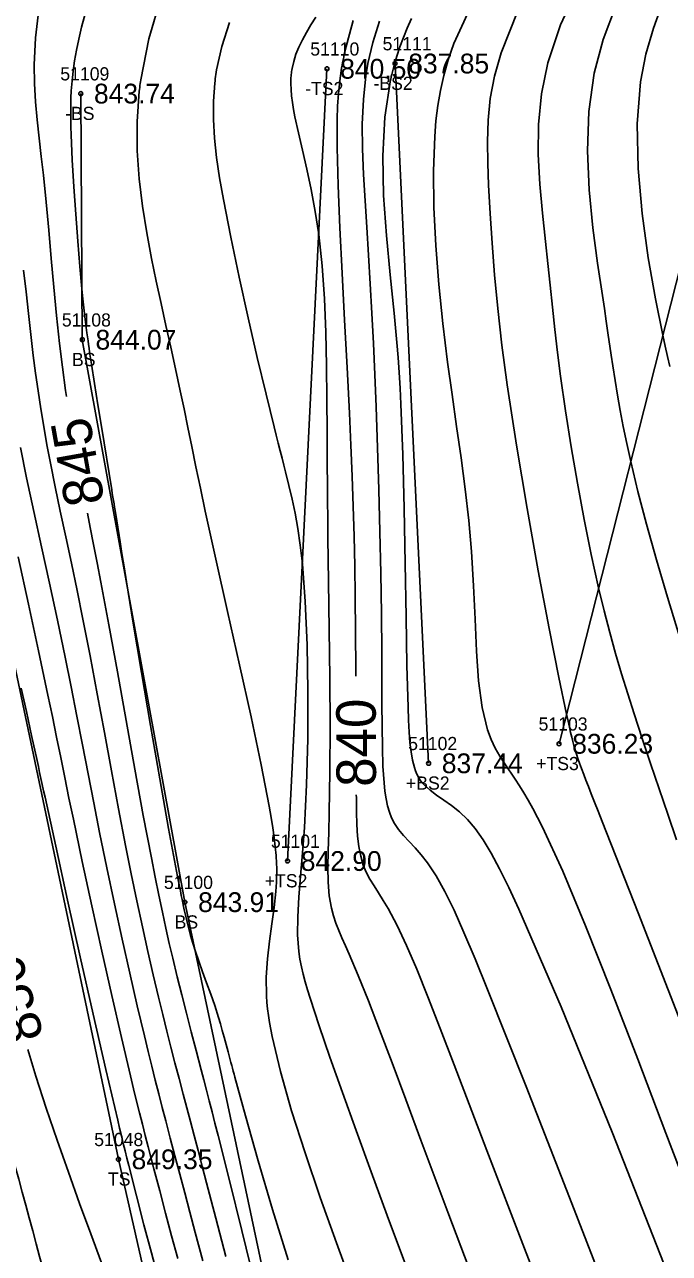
# Model space of a CAD drawing. Extents: x 1378535 to 1380697, y 997729 to 1000024.
# Drawn here: x 1380567 to 1380615.9, y 997912.8 to 998006 of the extents above; entities that cross this region are included whole.
import ezdxf

# ---------------------------------------------------------------- set-up
doc = ezdxf.new("R2010")
doc.units = 0
for name, color, linetype in [('RD_DTM_BkLn2', 7, 'Continuous'), ('RD_DTM_BkLn_txCode', 7, 'Continuous'), ('RD_DTM_Major1', 7, 'Continuous'), ('RD_DTM_Major1_Lbl', 7, 'Continuous'), ('RD_DTM_Minor1', 7, 'Continuous'), ('RD_EX_Road', 7, 'Continuous'), ('RD_EX_TX_Misc_ELEV', 7, 'Continuous'), ('RD_SMD_Locator', 7, 'Continuous')]:
    doc.layers.add(name, color=color, linetype=linetype)

msp = doc.modelspace()

# ---------------------------------------------------------------- linework, layer by layer
at = {"layer": 'RD_DTM_BkLn2'}
for p, q in [((1380586.934, 997942.589), (1380589.923, 998002.687)), ((1380597.628, 997950.001), (1380595.084, 998003.085)), ((1380607.515, 997951.483), (1380620.66, 998003.267))]:
    msp.add_line(p, q, dxfattribs=at)
for points in [[(1380613.928, 997764.375), (1380600.783, 997811.178), (1380584.607, 997873.664), (1380574.109, 997919.962), (1380555.718, 998007.419)], [(1380632.107, 997767.647), (1380611.875, 997813.248), (1380594.185, 997868.428), (1380579.15, 997939.468), (1380571.372, 997982.133), (1380571.255, 998000.803)]]:
    msp.add_lwpolyline(points, dxfattribs=at)
at = {"layer": 'RD_DTM_Major1'}
for points in [[(1380608.958, 998008.94), (1380607.632, 998006.019), (1380606.658, 998003.133), (1380606.178, 998000.785), (1380605.954, 997998.468), (1380605.93, 997996.185), (1380606.05, 997993.942), (1380606.257, 997991.744), (1380606.494, 997989.594), (1380606.674, 997987.92), (1380606.846, 997986.261), (1380607.019, 997984.595), (1380607.201, 997982.905), (1380607.402, 997981.169), (1380607.629, 997979.368), (1380608, 997976.741), (1380608.428, 997974.012), (1380608.904, 997971.243), (1380609.418, 997968.496), (1380609.959, 997965.832), (1380610.518, 997963.312), (1380610.938, 997961.569), (1380611.365, 997959.916), (1380611.802, 997958.33), (1380612.253, 997956.788), (1380612.721, 997955.267), (1380613.209, 997953.744), (1380613.824, 997951.884), (1380614.462, 997949.993), (1380615.114, 997948.077), (1380615.768, 997946.14), (1380616.415, 997944.189)], [(1380568.063, 998007.184), (1380567.83, 998005.04), (1380567.731, 998002.984), (1380567.746, 998001.568), (1380567.82, 998000.181), (1380567.939, 997998.809), (1380568.088, 997997.433), (1380568.254, 997996.039), (1380568.42, 997994.608), (1380568.631, 997992.566), (1380568.826, 997990.453), (1380569.015, 997988.297), (1380569.206, 997986.125), (1380569.41, 997983.967), (1380569.636, 997981.849), (1380569.858, 997980.044), (1380570.101, 997978.286), (1380570.171, 997977.831)], [(1380591.919, 998006.353), (1380591.283, 998003.998), (1380591.236, 998003.785), (1380591.191, 998003.573), (1380591.148, 998003.363), (1380591.107, 998003.155), (1380591.069, 998002.948), (1380591.033, 998002.743), (1380590.888, 998001.769), (1380590.788, 998000.808), (1380590.725, 997999.84), (1380590.694, 997998.847), (1380590.688, 997997.81), (1380590.7, 997996.711), (1380590.778, 997993.836), (1380590.907, 997990.621), (1380591.072, 997987.177), (1380591.256, 997983.611), (1380591.444, 997980.033), (1380591.618, 997976.552), (1380591.729, 997974.123), (1380591.825, 997971.778), (1380591.906, 997969.488), (1380591.973, 997967.227), (1380592.026, 997964.968), (1380592.066, 997962.684), (1380592.097, 997959.93), (1380592.114, 997957.17), (1380592.116, 997956.61)], [(1380571.756, 997968.973), (1380571.969, 997967.9), (1380572.228, 997966.595), (1380572.498, 997965.22), (1380572.78, 997963.754), (1380573.386, 997960.499), (1380574.029, 997956.948), (1380574.691, 997953.254), (1380575.353, 997949.568), (1380575.997, 997946.041), (1380576.605, 997942.824), (1380576.893, 997941.358), (1380577.17, 997939.994), (1380577.439, 997938.715), (1380577.703, 997937.503), (1380577.965, 997936.342), (1380578.228, 997935.216), (1380578.566, 997933.815), (1380578.912, 997932.428), (1380579.265, 997931.041), (1380579.628, 997929.64), (1380580.002, 997928.211), (1380580.387, 997926.738), (1380580.583, 997925.985), (1380580.784, 997925.21), (1380580.991, 997924.408), (1380581.205, 997923.571), (1380581.43, 997922.692), (1380581.665, 997921.765), (1380582.521, 997918.35), (1380583.46, 997914.566), (1380584.425, 997910.648)], [(1380592.147, 997947.61), (1380592.149, 997947.377), (1380592.162, 997946.323), (1380592.191, 997945.362), (1380592.245, 997944.485), (1380592.337, 997943.685), (1380592.477, 997942.954), (1380592.676, 997942.284), (1380592.904, 997941.743), (1380593.178, 997941.224), (1380593.488, 997940.707), (1380593.829, 997940.173), (1380594.19, 997939.604), (1380594.565, 997938.981), (1380595.243, 997937.707), (1380595.957, 997936.183), (1380596.727, 997934.386), (1380597.573, 997932.292), (1380598.515, 997929.878), (1380599.573, 997927.121), (1380602.05, 997920.629), (1380604.897, 997913.201), (1380607.942, 997905.357)], [(1380572.831, 997912.096), (1380572.014, 997914.3), (1380571.169, 997916.604), (1380570.314, 997918.981), (1380569.465, 997921.401), (1380568.641, 997923.836), (1380567.857, 997926.257), (1380567.234, 997928.284)]]:
    msp.add_lwpolyline(points, dxfattribs=at)
at = {"layer": 'RD_DTM_Minor1'}
for points in [[(1380572.144, 998008.889), (1380571.305, 998005.836), (1380571.097, 998004.934), (1380570.924, 998004.088), (1380570.784, 998003.285), (1380570.674, 998002.514), (1380570.593, 998001.763), (1380570.538, 998001.022), (1380570.513, 998000.49), (1380570.499, 997999.953), (1380570.495, 997999.408), (1380570.499, 997998.849), (1380570.511, 997998.275), (1380570.529, 997997.68), (1380570.612, 997995.769), (1380570.729, 997993.729), (1380570.872, 997991.645), (1380571.029, 997989.604), (1380571.191, 997987.691), (1380571.348, 997985.992), (1380571.423, 997985.238), (1380571.496, 997984.545), (1380571.569, 997983.895), (1380571.643, 997983.273), (1380571.722, 997982.661), (1380571.806, 997982.044), (1380571.845, 997981.766), (1380571.886, 997981.483), (1380571.929, 997981.194), (1380571.973, 997980.897), (1380572.019, 997980.593), (1380572.067, 997980.28), (1380572.296, 997978.806), (1380572.551, 997977.205), (1380572.821, 997975.539), (1380573.602, 997970.746), (1380573.647, 997970.471), (1380573.69, 997970.201), (1380573.733, 997969.937), (1380573.775, 997969.678), (1380573.816, 997969.422), (1380573.856, 997969.17), (1380573.979, 997968.398), (1380574.232, 997966.799), (1380574.374, 997965.907), (1380574.535, 997964.908), (1380574.72, 997963.77), (1380575.237, 997960.63), (1380575.862, 997956.902), (1380576.547, 997952.87), (1380577.248, 997948.822), (1380577.919, 997945.045), (1380578.513, 997941.825), (1380578.589, 997941.425), (1380578.663, 997941.041), (1380578.735, 997940.674), (1380578.805, 997940.322), (1380578.873, 997939.985), (1380578.939, 997939.663), (1380579.105, 997938.883), (1380579.264, 997938.18), (1380579.422, 997937.537), (1380579.582, 997936.938), (1380579.749, 997936.364), (1380579.926, 997935.8), (1380580.197, 997935.003), (1380580.49, 997934.189), (1380580.795, 997933.355), (1380581.105, 997932.499), (1380581.409, 997931.62), (1380581.701, 997930.714), (1380581.846, 997930.23), (1380581.988, 997929.732), (1380582.13, 997929.217), (1380582.275, 997928.678), (1380582.425, 997928.11), (1380582.584, 997927.507), (1380582.64, 997927.299), (1380582.696, 997927.087), (1380582.754, 997926.87), (1380582.814, 997926.648), (1380582.875, 997926.421), (1380582.937, 997926.189), (1380583.742, 997923.26), (1380584.711, 997919.855), (1380585.804, 997916.15), (1380586.982, 997912.323)], [(1380601.183, 998008.206), (1380599.548, 998004.598), (1380599.118, 998003.371), (1380598.779, 998002.189), (1380598.518, 998001.035), (1380598.324, 997999.89), (1380598.185, 997998.738), (1380598.089, 997997.56), (1380597.994, 997994.934), (1380598.026, 997992.159), (1380598.167, 997989.277), (1380598.399, 997986.332), (1380598.704, 997983.365), (1380599.066, 997980.42), (1380599.402, 997977.969), (1380599.747, 997975.554), (1380600.086, 997973.165), (1380600.4, 997970.793), (1380600.671, 997968.427), (1380600.883, 997966.059), (1380601.037, 997963.471), (1380601.147, 997960.932), (1380601.26, 997958.505), (1380601.423, 997956.255), (1380601.685, 997954.246), (1380602.092, 997952.541), (1380602.364, 997951.815), (1380602.677, 997951.159), (1380603.025, 997950.552), (1380603.399, 997949.97), (1380604.197, 997948.795), (1380604.52, 997948.299), (1380604.848, 997947.769), (1380605.184, 997947.198), (1380605.531, 997946.576), (1380605.891, 997945.896), (1380606.267, 997945.149), (1380607.794, 997941.818), (1380609.533, 997937.66), (1380611.443, 997932.848), (1380613.487, 997927.555), (1380615.624, 997921.953), (1380617.815, 997916.216)], [(1380577.338, 998008.175), (1380576.407, 998004.968), (1380575.802, 998001.853), (1380575.782, 998001.706), (1380575.762, 998001.56), (1380575.743, 998001.414), (1380575.725, 998001.269), (1380575.707, 998001.124), (1380575.691, 998000.979), (1380575.524, 997998.685), (1380575.529, 997996.471), (1380575.673, 997994.33), (1380575.925, 997992.258), (1380576.254, 997990.248), (1380576.629, 997988.294), (1380576.984, 997986.57), (1380577.346, 997984.878), (1380577.712, 997983.211), (1380578.079, 997981.559), (1380578.441, 997979.914), (1380578.796, 997978.268), (1380579.084, 997976.892), (1380579.372, 997975.486), (1380579.669, 997974.028), (1380579.983, 997972.497), (1380580.321, 997970.869), (1380580.692, 997969.123), (1380581.494, 997965.474), (1380582.381, 997961.524), (1380583.291, 997957.474), (1380584.163, 997953.526), (1380584.934, 997949.885), (1380585.542, 997946.751), (1380585.69, 997945.896), (1380585.816, 997945.103), (1380585.92, 997944.366), (1380586.001, 997943.674), (1380586.06, 997943.02), (1380586.097, 997942.395), (1380586.108, 997942.036), (1380586.111, 997941.681), (1380586.106, 997941.331), (1380586.095, 997940.982), (1380586.075, 997940.633), (1380586.049, 997940.282), (1380585.915, 997939.073), (1380585.738, 997937.82), (1380585.555, 997936.52), (1380585.402, 997935.176), (1380585.317, 997933.786), (1380585.336, 997932.35), (1380585.371, 997931.864), (1380585.422, 997931.37), (1380585.487, 997930.866), (1380585.567, 997930.349), (1380585.661, 997929.816), (1380585.768, 997929.266), (1380586.395, 997926.617), (1380587.24, 997923.649), (1380588.257, 997920.441), (1380589.404, 997917.071), (1380590.635, 997913.618), (1380591.907, 997910.16)], [(1380611.807, 998007.373), (1380610.867, 998004.909), (1380610.179, 998002.36), (1380609.767, 997999.444), (1380609.663, 997996.463), (1380609.792, 997993.498), (1380610.078, 997990.628), (1380610.443, 997987.934), (1380610.812, 997985.497), (1380610.962, 997984.495), (1380611.1, 997983.553), (1380611.228, 997982.659), (1380611.471, 997980.974), (1380611.59, 997980.162), (1380611.761, 997979.043), (1380611.945, 997977.917), (1380612.149, 997976.76), (1380612.38, 997975.552), (1380612.645, 997974.272), (1380612.951, 997972.899), (1380613.5, 997970.63), (1380614.151, 997968.134), (1380614.897, 997965.444), (1380615.73, 997962.592), (1380616.643, 997959.61)], [(1380615.369, 998007.67), (1380614.667, 998005.773), (1380614.098, 998003.795), (1380613.695, 998001.689), (1380613.448, 997998.509), (1380613.513, 997995.132), (1380613.814, 997991.699), (1380614.276, 997988.352), (1380614.825, 997985.234), (1380615.385, 997982.485), (1380615.566, 997981.652), (1380615.743, 997980.863), (1380615.92, 997980.102)], [(1380589.072, 998006.612), (1380588.71, 998006.031), (1380588.363, 998005.442), (1380588.056, 998004.876), (1380587.791, 998004.324), (1380587.572, 998003.783), (1380587.399, 998003.244), (1380587.275, 998002.703), (1380587.256, 998002.591), (1380587.239, 998002.477), (1380587.224, 998002.364), (1380587.212, 998002.249), (1380587.201, 998002.134), (1380587.193, 998002.018), (1380587.18, 998001.575), (1380587.195, 998001.115), (1380587.236, 998000.635), (1380587.301, 998000.13), (1380587.387, 997999.596), (1380587.494, 997999.031), (1380587.751, 997997.835), (1380588.055, 997996.514), (1380588.384, 997995.074), (1380588.716, 997993.524), (1380589.028, 997991.871), (1380589.298, 997990.123), (1380589.561, 997987.735), (1380589.735, 997985.246), (1380589.84, 997982.7), (1380589.895, 997980.141), (1380589.917, 997977.615), (1380589.927, 997975.165), (1380589.933, 997973.851), (1380589.942, 997972.554), (1380589.952, 997971.253), (1380589.965, 997969.93), (1380589.98, 997968.563), (1380589.998, 997967.131), (1380590.044, 997963.767), (1380590.092, 997960.157), (1380590.132, 997956.45), (1380590.154, 997952.799), (1380590.146, 997949.352), (1380590.098, 997946.261), (1380590.054, 997944.743), (1380590.014, 997943.367), (1380589.995, 997942.12), (1380590.016, 997940.987), (1380590.097, 997939.955), (1380590.256, 997939.007), (1380590.407, 997938.436), (1380590.593, 997937.879), (1380590.81, 997937.325), (1380591.054, 997936.758), (1380591.319, 997936.165), (1380591.602, 997935.531), (1380592.295, 997933.898), (1380593.062, 997931.982), (1380593.912, 997929.779), (1380594.853, 997927.284), (1380595.893, 997924.494), (1380597.041, 997921.404), (1380599.077, 997915.943), (1380601.33, 997909.999)], [(1380596.332, 998006.508), (1380596.01, 998005.773), (1380595.719, 998005.056), (1380595.457, 998004.35), (1380595.223, 998003.65), (1380595.015, 998002.951), (1380594.833, 998002.248), (1380594.801, 998002.113), (1380594.786, 998002.045), (1380594.755, 998001.908), (1380594.74, 998001.84), (1380594.304, 997999.012), (1380594.152, 997996.071), (1380594.217, 997993.067), (1380594.429, 997990.047), (1380594.719, 997987.061), (1380595.018, 997984.158), (1380595.125, 997983.032), (1380595.223, 997981.914), (1380595.312, 997980.788), (1380595.393, 997979.642), (1380595.465, 997978.461), (1380595.531, 997977.233), (1380595.679, 997973.429), (1380595.785, 997969.332), (1380595.861, 997965.155), (1380595.924, 997961.11), (1380595.987, 997957.408), (1380596.066, 997954.263), (1380596.104, 997953.264), (1380596.152, 997952.367), (1380596.214, 997951.568), (1380596.297, 997950.86), (1380596.406, 997950.237), (1380596.547, 997949.694), (1380596.641, 997949.424), (1380596.747, 997949.174), (1380596.866, 997948.943), (1380597, 997948.729), (1380597.148, 997948.529), (1380597.313, 997948.342), (1380597.74, 997947.954), (1380598.235, 997947.589), (1380598.782, 997947.216), (1380599.364, 997946.805), (1380599.966, 997946.326), (1380600.57, 997945.749), (1380601.161, 997945.051), (1380601.755, 997944.206), (1380602.368, 997943.194), (1380603.015, 997941.993), (1380603.713, 997940.584), (1380604.477, 997938.945), (1380607.685, 997931.528), (1380611.555, 997922.009), (1380615.763, 997911.263)], [(1380604.405, 998007.077), (1380603.12, 998003.905), (1380602.623, 998002.136), (1380602.306, 998000.439), (1380602.138, 997998.787), (1380602.083, 997997.156), (1380602.108, 997995.519), (1380602.18, 997993.85), (1380602.294, 997991.715), (1380602.439, 997989.464), (1380602.628, 997987.067), (1380602.873, 997984.493), (1380603.188, 997981.714), (1380603.586, 997978.699), (1380604.28, 997974.125), (1380605.089, 997969.329), (1380605.943, 997964.601), (1380606.772, 997960.231), (1380607.509, 997956.51), (1380608.084, 997953.726), (1380608.199, 997953.193), (1380608.3, 997952.73), (1380608.392, 997952.327), (1380608.477, 997951.972), (1380608.558, 997951.653), (1380608.637, 997951.36), (1380608.734, 997951.027), (1380608.837, 997950.699), (1380608.95, 997950.362), (1380609.079, 997950.003), (1380609.225, 997949.605), (1380609.395, 997949.156), (1380609.561, 997948.722), (1380609.749, 997948.232), (1380609.963, 997947.681), (1380610.205, 997947.059), (1380610.477, 997946.362), (1380610.783, 997945.58), (1380613.504, 997938.661), (1380617.314, 997928.92)], [(1380582.534, 998006.186), (1380581.957, 998004.387), (1380581.558, 998002.602), (1380581.53, 998002.433), (1380581.503, 998002.265), (1380581.479, 998002.097), (1380581.455, 998001.929), (1380581.434, 998001.761), (1380581.414, 998001.593), (1380581.312, 998000.224), (1380581.308, 997998.84), (1380581.393, 997997.421), (1380581.555, 997995.949), (1380581.784, 997994.405), (1380582.067, 997992.77), (1380582.62, 997989.905), (1380583.255, 997986.873), (1380583.937, 997983.796), (1380584.631, 997980.796), (1380585.302, 997977.995), (1380585.914, 997975.515), (1380586.074, 997974.883), (1380586.226, 997974.283), (1380586.372, 997973.71), (1380586.512, 997973.16), (1380586.648, 997972.629), (1380586.78, 997972.112), (1380587.04, 997971.074), (1380587.283, 997970.039), (1380587.508, 997968.968), (1380587.714, 997967.821), (1380587.897, 997966.56), (1380588.056, 997965.144), (1380588.271, 997962.271), (1380588.41, 997958.987), (1380588.472, 997955.461), (1380588.459, 997951.863), (1380588.371, 997948.361), (1380588.21, 997945.126), (1380588.066, 997943.198), (1380587.917, 997941.442), (1380587.788, 997939.836), (1380587.706, 997938.36), (1380587.698, 997936.995), (1380587.789, 997935.718), (1380587.874, 997935.14), (1380587.984, 997934.569), (1380588.119, 997933.996), (1380588.275, 997933.413), (1380588.452, 997932.811), (1380588.647, 997932.183), (1380589.331, 997930.088), (1380590.149, 997927.697), (1380591.088, 997925.037), (1380592.133, 997922.134), (1380593.273, 997919.013), (1380594.492, 997915.701), (1380596.102, 997911.369)], [(1380593.895, 998006.289), (1380593.397, 998004.678), (1380593.029, 998003.076), (1380592.973, 998002.767), (1380592.921, 998002.457), (1380592.874, 998002.146), (1380592.681, 998000.345), (1380592.602, 997998.496), (1380592.613, 997996.601), (1380592.689, 997994.661), (1380592.806, 997992.68), (1380592.941, 997990.659), (1380593.076, 997988.539), (1380593.204, 997986.371), (1380593.325, 997984.146), (1380593.439, 997981.854), (1380593.545, 997979.488), (1380593.645, 997977.037), (1380593.757, 997973.942), (1380593.857, 997970.768), (1380593.942, 997967.572), (1380594.01, 997964.413), (1380594.057, 997961.349), (1380594.083, 997958.438), (1380594.088, 997956.431), (1380594.089, 997954.549), (1380594.097, 997952.804), (1380594.12, 997951.209), (1380594.169, 997949.773), (1380594.252, 997948.51), (1380594.319, 997947.885), (1380594.404, 997947.311), (1380594.513, 997946.785), (1380594.651, 997946.303), (1380594.823, 997945.858), (1380595.035, 997945.446), (1380595.354, 997944.975), (1380595.73, 997944.523), (1380596.148, 997944.068), (1380596.599, 997943.586), (1380597.069, 997943.054), (1380597.546, 997942.447), (1380598.193, 997941.468), (1380598.855, 997940.281), (1380599.553, 997938.854), (1380600.311, 997937.16), (1380601.151, 997935.168), (1380602.096, 997932.85), (1380605.024, 997925.475), (1380608.49, 997916.598), (1380612.205, 997907.032)], [(1380582.255, 997912.577), (1380581.496, 997915.502), (1380580.794, 997918.189), (1380580.463, 997919.448), (1380580.15, 997920.633), (1380579.852, 997921.757), (1380579.567, 997922.833), (1380579.29, 997923.875), (1380579.02, 997924.896), (1380578.708, 997926.082), (1380578.398, 997927.269), (1380578.09, 997928.469), (1380577.78, 997929.692), (1380577.468, 997930.949), (1380577.152, 997932.251), (1380576.75, 997933.948), (1380576.341, 997935.733), (1380575.925, 997937.607), (1380575.504, 997939.569), (1380575.079, 997941.621), (1380574.651, 997943.763), (1380574.118, 997946.544), (1380573.582, 997949.419), (1380573.044, 997952.342), (1380572.504, 997955.267), (1380571.962, 997958.147), (1380571.418, 997960.937), (1380570.977, 997963.106), (1380570.54, 997965.189), (1380570.115, 997967.192), (1380569.705, 997969.118), (1380569.318, 997970.973), (1380568.96, 997972.76), (1380568.693, 997974.168), (1380568.447, 997975.545), (1380568.221, 997976.901), (1380568.013, 997978.246), (1380567.822, 997979.592), (1380567.647, 997980.948), (1380567.463, 997982.519), (1380567.285, 997984.12), (1380567.103, 997985.754), (1380566.904, 997987.422)], [(1380580.506, 997912.26), (1380579.939, 997914.421), (1380579.533, 997915.957), (1380579.142, 997917.428), (1380578.764, 997918.845), (1380578.399, 997920.217), (1380578.045, 997921.555), (1380577.699, 997922.868), (1380577.433, 997923.89), (1380577.168, 997924.916), (1380576.903, 997925.96), (1380576.634, 997927.033), (1380576.359, 997928.151), (1380576.075, 997929.325), (1380575.534, 997931.611), (1380574.967, 997934.077), (1380574.386, 997936.673), (1380573.803, 997939.352), (1380573.229, 997942.065), (1380572.677, 997944.764), (1380572.236, 997946.995), (1380571.81, 997949.198), (1380571.391, 997951.39), (1380570.968, 997953.587), (1380570.533, 997955.805), (1380570.078, 997958.062), (1380569.492, 997960.849), (1380568.885, 997963.658), (1380568.278, 997966.433), (1380567.693, 997969.114), (1380567.152, 997971.645), (1380566.677, 997973.968)], [(1380578.607, 997912.44), (1380578.146, 997914.16), (1380577.689, 997915.867), (1380577.237, 997917.561), (1380576.793, 997919.242), (1380576.359, 997920.911), (1380576.141, 997921.76), (1380575.925, 997922.615), (1380575.707, 997923.486), (1380575.485, 997924.381), (1380575.259, 997925.31), (1380575.024, 997926.283), (1380574.338, 997929.197), (1380573.604, 997932.393), (1380572.847, 997935.76), (1380572.093, 997939.186), (1380571.366, 997942.558), (1380570.692, 997945.765), (1380570.362, 997947.365), (1380570.047, 997948.916), (1380569.737, 997950.444), (1380569.426, 997951.978), (1380569.105, 997953.545), (1380568.767, 997955.173), (1380568.053, 997958.533), (1380567.283, 997962.076), (1380566.496, 997965.655)], [(1380577.156, 997910.833), (1380576.605, 997912.876), (1380576.043, 997914.994), (1380575.47, 997917.197), (1380574.888, 997919.499), (1380574.752, 997920.046), (1380574.615, 997920.6), (1380574.477, 997921.163), (1380574.337, 997921.736), (1380574.196, 997922.32), (1380574.053, 997922.918), (1380573.145, 997926.778), (1380572.185, 997930.969), (1380571.208, 997935.311), (1380570.252, 997939.622), (1380569.352, 997943.72), (1380568.546, 997947.422), (1380568.44, 997947.91), (1380568.337, 997948.387), (1380568.236, 997948.854), (1380568.137, 997949.311), (1380568.039, 997949.761), (1380567.943, 997950.203), (1380567.529, 997952.105), (1380567.13, 997953.92), (1380566.734, 997955.69)]]:
    msp.add_lwpolyline(points, dxfattribs=at)
at = {"layer": 'RD_EX_Road'}
msp.add_spline([(1380571.276, 997900.848), (1380553.838, 997963.229), (1380535.074, 998018.791), (1380510.809, 998079.184), (1380486.363, 998133.158), (1380458.393, 998185.941), (1380428.109, 998238.221), (1380392.689, 998291.143), (1380357.52, 998337.623), (1380319.367, 998385.164), (1380279.255, 998428.684), (1380239.596, 998468.129), (1380183.367, 998518.832)], degree=3, dxfattribs=at)
at = {"layer": 'RD_SMD_Locator'}
for centre in [(1380589.923, 998002.687), (1380595.084, 998003.085), (1380571.255, 998000.803), (1380571.372, 997982.133), (1380607.515, 997951.483), (1380597.628, 997950.001), (1380586.934, 997942.589), (1380579.15, 997939.468), (1380574.109, 997919.962)]:
    msp.add_circle(centre, 0.15, dxfattribs=at)

# ---------------------------------------------------------------- texts
at = {"layer": 'RD_DTM_BkLn_txCode'}
for s, p in [('51110', (1380588.655, 998003.687)), ('51111', (1380594.139, 998004.085)), ('51109', (1380569.704, 998001.803)), ('-TS2', (1380588.269, 998000.687)), ('-BS2', (1380593.446, 998001.085)), ('-BS', (1380570.066, 997998.803)), ('51108', (1380569.821, 997983.133)), ('BS', (1380570.592, 997980.133)), ('51103', (1380605.964, 997952.483)), ('51102', (1380596.077, 997951.001)), ('+TS3', (1380605.783, 997949.483)), ('+BS2', (1380595.911, 997948.001)), ('51101', (1380585.666, 997943.589)), ('51100', (1380577.559, 997940.468)), ('+TS2', (1380585.202, 997940.589)), ('BS', (1380578.37, 997937.468)), ('51048', (1380572.274, 997920.962)), ('TS', (1380573.314, 997917.962))]:
    msp.add_text(s, height=1, dxfattribs=at).set_placement(p)
at = {"layer": 'RD_DTM_Major1_Lbl'}
for s, rotation, p in [('845', 100.14451, (1380573.071, 997969.82)), ('840', 90.19834, (1380593.642, 997948.218)), ('850', 105.61482, (1380568.483, 997929.258))]:
    msp.add_text(s, height=3, rotation=rotation, dxfattribs=at).set_placement(p)
at = {"layer": 'RD_EX_TX_Misc_ELEV'}
for s, p in [('837.85', (1380596.084, 998002.335)), ('840.50', (1380590.923, 998001.937)), ('843.74', (1380572.255, 998000.053)), ('844.07', (1380572.372, 997981.383)), ('836.23', (1380608.515, 997950.733)), ('837.44', (1380598.628, 997949.251)), ('842.90', (1380587.934, 997941.839)), ('843.91', (1380580.15, 997938.718)), ('849.35', (1380575.109, 997919.212))]:
    msp.add_text(s, height=1.5, dxfattribs=at).set_placement(p)

doc.saveas('drawing.dxf')
